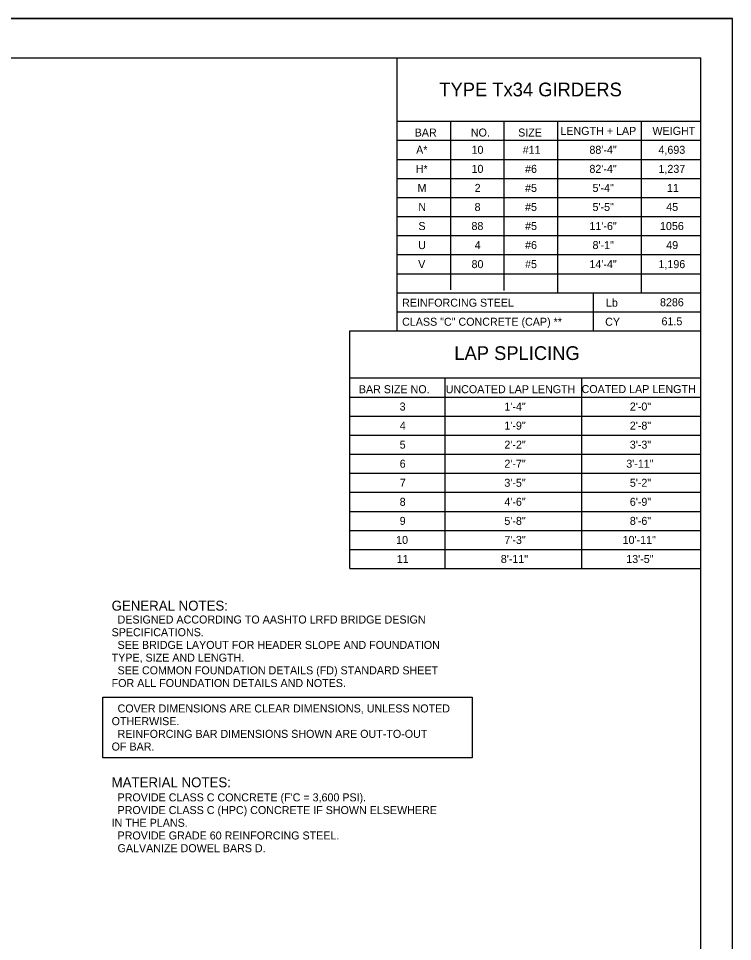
# Model space of a CAD drawing. Extents: x 926 to 1074, y 990 to 1081.
# Drawn here: x 1022.76 to 1034, y 1007.47 to 1022 of the extents above; entities that cross this region are included whole.
import ezdxf

# ---------------------------------------------------------------- set-up
doc = ezdxf.new("R2010")
doc.units = 0
for name, color, linetype in [('BORD_lines_major', 7, 'Continuous'), ('D_BATCH_PLOT', 7, 'Continuous'), ('D_SHEET', 7, 'Continuous'), ('Default', 7, 'Continuous'), ('Working Level 1', 7, 'Continuous')]:
    doc.layers.add(name, color=color, linetype=linetype)

msp = doc.modelspace()

# ---------------------------------------------------------------- linework, layer by layer
at = {"layer": 'BORD_lines_major'}
for p in [(1002.413, 1021.382), (1033.5, 1000.5)]:
    msp.add_line(p, (1033.5, 1021.382), dxfattribs=at)
at = {"layer": 'D_BATCH_PLOT'}
msp.add_lwpolyline([(1000, 1000), (1034, 1000), (1034, 1022), (1000, 1022)], close=True, dxfattribs=at)
at = {"layer": 'D_SHEET'}
for p in [(1000, 1022), (1034, 1000)]:
    msp.add_line(p, (1034, 1022), dxfattribs=at)
at = {"layer": 'Default'}
for p in [(1029.876, 1021.382), (1033.5, 1014.142)]:
    msp.add_line(p, (1033.5, 1021.382), dxfattribs=at)
at = {"layer": 'Working Level 1'}
for p, q in [((1028.719, 1017.082), (1028.719, 1021.382)), ((1028.719, 1021.382), (1033.5, 1021.382)), ((1028.783, 1021.382), (1033.5, 1021.382)), ((1028.783, 1021.382), (1033.5, 1021.382)), ((1033.5, 1015.839), (1033.5, 1021.382)), ((1033.5, 1017.682), (1033.5, 1021.382)), ((1028.719, 1020.382), (1033.5, 1020.382)), ((1029.563, 1017.725), (1029.563, 1020.382)), ((1030.406, 1017.715), (1030.406, 1020.382)), ((1031.25, 1017.675), (1031.25, 1020.382)), ((1032.568, 1017.682), (1032.568, 1020.382)), ((1028.719, 1020.082), (1033.5, 1020.082)), ((1028.719, 1019.782), (1033.5, 1019.782)), ((1028.719, 1019.482), (1033.5, 1019.482)), ((1028.719, 1019.182), (1033.5, 1019.182)), ((1028.719, 1018.882), (1033.5, 1018.882)), ((1028.719, 1018.582), (1033.5, 1018.582)), ((1028.719, 1018.282), (1033.5, 1018.282)), ((1028.719, 1017.982), (1033.5, 1017.982)), ((1028.719, 1017.682), (1033.5, 1017.682)), ((1031.813, 1017.082), (1031.813, 1017.682)), ((1028.719, 1017.382), (1033.5, 1017.382)), ((1027.975, 1013.34), (1027.975, 1017.082)), ((1027.975, 1017.082), (1033.5, 1017.082)), ((1028.719, 1017.082), (1033.5, 1017.082)), ((1028.719, 1017.082), (1033.5, 1017.082)), ((1033.5, 1013.34), (1033.5, 1017.082)), ((1027.975, 1016.34), (1033.5, 1016.34)), ((1029.475, 1013.34), (1029.475, 1016.34)), ((1031.625, 1013.34), (1031.625, 1016.34)), ((1027.975, 1016.04), (1033.5, 1016.04)), ((1027.975, 1015.74), (1033.5, 1015.74)), ((1027.975, 1015.44), (1033.5, 1015.44)), ((1027.975, 1015.14), (1033.5, 1015.14)), ((1027.975, 1014.84), (1033.5, 1014.84)), ((1027.975, 1014.54), (1033.5, 1014.54)), ((1027.975, 1014.24), (1033.5, 1014.24)), ((1027.975, 1013.94), (1033.5, 1013.94)), ((1027.975, 1013.64), (1033.5, 1013.64)), ((1027.975, 1013.34), (1033.5, 1013.34))]:
    msp.add_line(p, q, dxfattribs=at)
msp.add_lwpolyline([(1024.084, 1011.317), (1029.903, 1011.317), (1029.903, 1010.357), (1024.084, 1010.357)], close=True, dxfattribs=at)

# ---------------------------------------------------------------- texts
for s, height, p in [('TYPE Tx34 GIRDERS', 0.216, (1029.384, 1020.774)), ('BAR', 0.126, (1028.996, 1020.141)), ('NO.', 0.126, (1029.88, 1020.141)), ('SIZE', 0.126, (1030.625, 1020.141)), ('LENGTH + LAP', 0.126, (1031.29, 1020.167)), ('WEIGHT', 0.126, (1032.739, 1020.167)), ('A*', 0.126, (1029.019, 1019.869)), ('10', 0.126, (1029.891, 1019.869)), ('#11', 0.126, (1030.697, 1019.869)), ('88\'-4"', 0.126, (1031.747, 1019.869)), ('4,693', 0.126, (1032.834, 1019.869)), ('H*', 0.126, (1029.014, 1019.569)), ('10', 0.126, (1029.891, 1019.569)), ('#6', 0.126, (1030.734, 1019.569)), ('82\'-4"', 0.126, (1031.747, 1019.569)), ('1,237', 0.126, (1032.834, 1019.569)), ('M', 0.126, (1029.042, 1019.269)), ('2', 0.126, (1029.94, 1019.269)), ('#5', 0.126, (1030.734, 1019.269)), ('5\'-4"', 0.126, (1031.796, 1019.269)), ('11', 0.126, (1032.968, 1019.269)), ('N', 0.126, (1029.053, 1018.969)), ('8', 0.126, (1029.939, 1018.969)), ('#5', 0.126, (1030.734, 1018.969)), ('5\'-5"', 0.126, (1031.796, 1018.969)), ('45', 0.126, (1032.956, 1018.969)), ('S', 0.126, (1029.055, 1018.669)), ('88', 0.126, (1029.89, 1018.669)), ('#5', 0.126, (1030.734, 1018.669)), ('11\'-6"', 0.126, (1031.747, 1018.669)), ('1056', 0.126, (1032.858, 1018.669)), ('U', 0.126, (1029.052, 1018.369)), ('4', 0.126, (1029.94, 1018.369)), ('#6', 0.126, (1030.734, 1018.369)), ('8\'-1"', 0.126, (1031.796, 1018.369)), ('49', 0.126, (1032.956, 1018.369)), ('V', 0.126, (1029.051, 1018.069)), ('80', 0.126, (1029.891, 1018.069)), ('#5', 0.126, (1030.734, 1018.069)), ('14\'-4"', 0.126, (1031.747, 1018.069)), ('1,196', 0.126, (1032.834, 1018.069)), ('REINFORCING STEEL', 0.126, (1028.798, 1017.462)), ('Lb', 0.126, (1032.007, 1017.462)), ('8286', 0.126, (1032.858, 1017.469)), ('61.5', 0.126, (1032.882, 1017.169)), ('CLASS "C" CONCRETE (CAP) **', 0.126, (1028.798, 1017.162)), ('CY', 0.126, (1031.995, 1017.162)), ('LAP SPLICING', 0.216, (1029.62, 1016.623)), ('BAR SIZE NO.', 0.126, (1028.117, 1016.1)), ('UNCOATED LAP LENGTH', 0.126, (1029.484, 1016.1)), ('COATED LAP LENGTH', 0.126, (1031.623, 1016.102)), ('3', 0.126, (1028.759, 1015.827)), ('1\'-4"', 0.126, (1030.408, 1015.827)), ('2\'-0"', 0.126, (1032.383, 1015.827)), ('4', 0.126, (1028.762, 1015.527)), ('1\'-9"', 0.126, (1030.408, 1015.527)), ('2\'-8"', 0.126, (1032.383, 1015.527)), ('5', 0.126, (1028.76, 1015.227)), ('2\'-2"', 0.126, (1030.408, 1015.227)), ('3\'-3"', 0.126, (1032.383, 1015.227)), ('6', 0.126, (1028.76, 1014.927)), ('2\'-7"', 0.126, (1030.408, 1014.927)), ('3\'-11"', 0.126, (1032.327, 1014.927)), ('7', 0.126, (1028.762, 1014.627)), ('3\'-5"', 0.126, (1030.408, 1014.627)), ('5\'-2"', 0.126, (1032.383, 1014.627)), ('8', 0.126, (1028.76, 1014.327)), ('4\'-6"', 0.126, (1030.408, 1014.327)), ('6\'-9"', 0.126, (1032.383, 1014.327)), ('9', 0.126, (1028.76, 1014.027)), ('5\'-8"', 0.126, (1030.408, 1014.027)), ('8\'-6"', 0.126, (1032.383, 1014.027)), ('10', 0.126, (1028.704, 1013.727)), ('7\'-3"', 0.126, (1030.408, 1013.727)), ('10\'-11"', 0.126, (1032.27, 1013.727)), ('11', 0.126, (1028.714, 1013.427)), ('8\'-11"', 0.126, (1030.352, 1013.427)), ('13\'-5"', 0.126, (1032.327, 1013.427)), ('GENERAL NOTES:', 0.156, (1024.225, 1012.677)), ('  DESIGNED ACCORDING TO AASHTO LRFD BRIDGE DESIGN', 0.126, (1024.225, 1012.474)), ('SPECIFICATIONS.', 0.126, (1024.225, 1012.274)), ('  SEE BRIDGE LAYOUT FOR HEADER SLOPE AND FOUNDATION', 0.126, (1024.225, 1012.074)), ('TYPE, SIZE AND LENGTH. ', 0.126, (1024.225, 1011.874)), ('  SEE COMMON FOUNDATION DETAILS (FD) STANDARD SHEET', 0.126, (1024.225, 1011.674)), ('FOR ALL FOUNDATION DETAILS AND NOTES.', 0.126, (1024.225, 1011.474)), ('  COVER DIMENSIONS ARE CLEAR DIMENSIONS, UNLESS NOTED', 0.126, (1024.225, 1011.074)), ('OTHERWISE.', 0.126, (1024.225, 1010.874)), ('  REINFORCING BAR DIMENSIONS SHOWN ARE OUT-TO-OUT', 0.126, (1024.225, 1010.674)), ('OF BAR.', 0.126, (1024.225, 1010.474)), ('MATERIAL NOTES:', 0.156, (1024.225, 1009.896)), ("  PROVIDE CLASS C CONCRETE (F'C = 3,600 PSI).", 0.126, (1024.225, 1009.674)), ('  PROVIDE CLASS C (HPC) CONCRETE IF SHOWN ELSEWHERE', 0.126, (1024.225, 1009.474)), ('IN THE PLANS.', 0.126, (1024.225, 1009.274)), ('  PROVIDE GRADE 60 REINFORCING STEEL.', 0.126, (1024.225, 1009.074)), ('  GALVANIZE DOWEL BARS D.', 0.126, (1024.225, 1008.874))]:
    msp.add_text(s, height=height, dxfattribs=at).set_placement(p)

doc.saveas('drawing.dxf')
